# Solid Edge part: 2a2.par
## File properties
Author: edge
Template: jis part.par
Last saved by: edge
Revision: 21
Application: Solid Edge
Accuracy: 0.990
文書内容のタイプ: 0
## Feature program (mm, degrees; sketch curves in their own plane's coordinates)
sketch for "unnamed Protrusion 1" plane through (0, 0, 0) normal (1, 0, 0) x-axis (0, 1, 0)
  line (0, 0) -> (-80, 0)
  line (-80, 0) -> (-80, 180)
  line (-80, 180) -> (0, 180)
  line (0, 180) -> (0, 0)
extrude "unnamed Protrusion 1" add finite 160 symmetric
thinwall "Thinwall_1"  Thickness = 20 mm
sketch for "unnamed Cutout 1" plane through (0, 0, 0) normal (0, -1, 0) x-axis (1, 0, 0)
  circle centre (0, 120) radius 27.5
extrude "unnamed Cutout 1" cut through
sketch for "unnamed Cutout 2" #1 plane through (0, 0, 0) normal (0, -1, 0) x-axis (1, 0, 0)
sketch for "unnamed Cutout 2" #2 plane through (0, 0, 0) normal (0, -1, 0) x-axis (1, 0, 0)
  circle centre (-50, 120) radius 6
extrude "unnamed Cutout 2" cut through along +normal
sketch for "unnamed Cutout 3" #1 plane through (0, 0, 0) normal (0, 0, 1) x-axis (1, 0, 0)
sketch for "unnamed Cutout 3" #2 plane through (0, 0, 0) normal (0, 0, 1) x-axis (1, 0, 0)
extrude "unnamed Cutout 3" cut through along +normal
chamfer "Chamfer_1" setback 5
chamfer "Chamfer_2" setback 5
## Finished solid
Body 1: solid body, 17 faces, 40 edges, 20 vertices.
  Faces by surface: plane 12, cylinder 5
  Edges by curve: line 30, circle 10
Bounding box of the edges (mm): 160.000 x 80.000 x 180.000, from (-80, -80, 0) to (80, 0, 180).
Cylindrical faces by radius (mm): R6 x2, R7.5 x2, R27.5 x1
Planar faces by outward normal: +x 1, +y 1, +z 2, -x 1, -y 2, -z 1, oblique 4
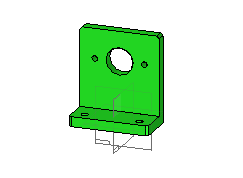
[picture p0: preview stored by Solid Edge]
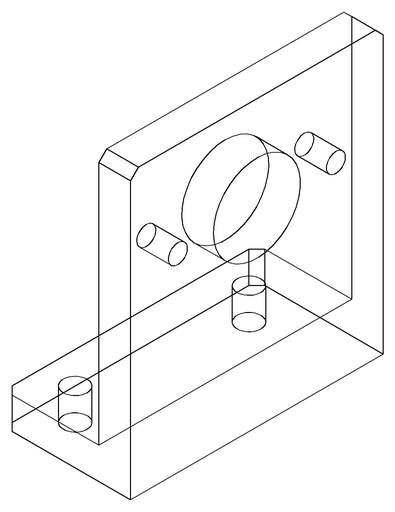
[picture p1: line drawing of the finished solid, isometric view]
